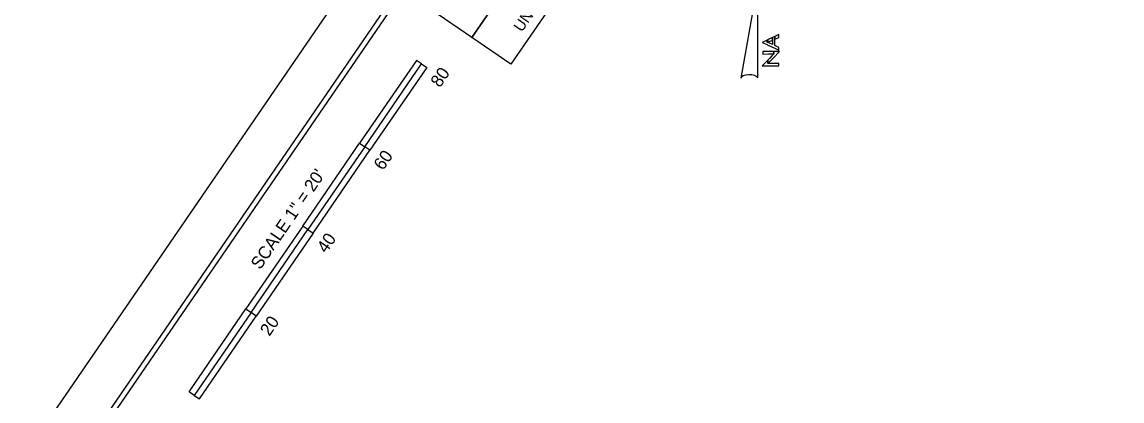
# Model space of a CAD drawing. Extents: x 1439200 to 1641919, y 393684 to 606444.
# Drawn here: x 1641394.1 to 1641613.1, y 394263 to 394338.4 of the extents above; entities that cross this region are included whole.
import ezdxf

# ---------------------------------------------------------------- set-up
doc = ezdxf.new("R2010")
doc.units = 0
for name, color, linetype in [('North Arrow NAD83 CELL', 7, 'Continuous'), ('Old_Level_20', 7, 'Continuous'), ('Old_Level_60', 7, 'Continuous'), ('Sheet Plot Border Inside CELL', 7, 'Continuous'), ('Sheet Plot Border Outside CELL', 7, 'Continuous'), ('Sheet Sticker Exception Certification CELL', 7, 'Continuous'), ('UC Plan Sheet 34 CELL', 7, 'Continuous')]:
    doc.layers.add(name, color=color, linetype=linetype)

msp = doc.modelspace()

# ---------------------------------------------------------------- linework, layer by layer
at = {"layer": 'North Arrow NAD83 CELL'}
for p, q in [((1641540.57, 394346.11), (1641537.22, 394327.22)), ((1641540.58, 394327.29), (1641540.57, 394346.11))]:
    msp.add_line(p, q, dxfattribs=at)
for points in [[(1641543.96, 394333.21), (1641544.78, 394332.83), (1641544.78, 394333.38), (1641543.96, 394333.74), (1641543.96, 394335.53), (1641543.53, 394335.33), (1641543.53, 394333.94), (1641542.8, 394334.26), (1641542.8, 394334.26), (1641542.62, 394334.33), (1641542.61, 394334.33), (1641542.44, 394334.38), (1641542.44, 394334.82), (1641541.47, 394334.37), (1641542.44, 394333.92), (1641542.62, 394333.84), (1641542.62, 394333.84), (1641542.8, 394333.75), (1641542.8, 394333.75), (1641543.53, 394333.41)], [(1641542.44, 394334.38), (1641542.61, 394334.43), (1641542.61, 394334.9), (1641542.44, 394334.82)], [(1641542.8, 394334.5), (1641543.53, 394334.82), (1641543.53, 394335.33), (1641542.8, 394334.99), (1641542.8, 394334.99), (1641542.62, 394334.9), (1641542.61, 394334.9), (1641542.61, 394334.43), (1641542.62, 394334.43), (1641542.8, 394334.5)], [(1641543.96, 394335), (1641544.78, 394335.37), (1641544.78, 394335.91), (1641543.96, 394335.53)], [(1641543.6, 394332.06), (1641543.8, 394332.06), (1641543.8, 394332.53), (1641543.6, 394332.53), (1641543.42, 394332.53), (1641542.92, 394332.53), (1641542.73, 394332.53), (1641541.6, 394332.53), (1641541.6, 394332.05), (1641542.73, 394332.06), (1641542.92, 394332.06), (1641543.42, 394332.06)], [(1641544.78, 394332.4), (1641544.9, 394332.53), (1641544.78, 394332.53), (1641543.8, 394332.53), (1641543.8, 394332.06), (1641543.6, 394331.88), (1641543.42, 394331.71), (1641542.92, 394331.19), (1641542.73, 394330.99), (1641542.57, 394330.83), (1641542.57, 394330.16), (1641542.73, 394330.29), (1641542.92, 394330.47), (1641543.42, 394330.99), (1641543.6, 394331.17), (1641543.8, 394331.39)], [(1641543.8, 394329.69), (1641544.78, 394329.69), (1641544.78, 394330.16), (1641543.8, 394330.16), (1641543.6, 394330.16), (1641543.42, 394330.16), (1641542.92, 394330.16), (1641542.73, 394330.16), (1641542.57, 394330.16), (1641542.57, 394330.83), (1641541.47, 394329.69), (1641542.57, 394329.69), (1641542.73, 394329.69), (1641542.92, 394329.69), (1641543.42, 394329.69), (1641543.6, 394329.69)]]:
    msp.add_lwpolyline(points, close=True, dxfattribs=at)
msp.add_ellipse((1641538.92, 394327.15), major_axis=(1.69, -0.01), ratio=0.461098, start_param=0.201328, end_param=3.141593, dxfattribs=at)
at = {"layer": 'Old_Level_20'}
for points in [[(1641462.35, 394313.59), (1641473.66, 394330.09), (1641472.63, 394330.79), (1641461.32, 394314.3), (1641462.35, 394313.59)], [(1641452.07, 394296.39), (1641463.38, 394312.89), (1641462.35, 394313.59), (1641451.04, 394297.1), (1641452.07, 394296.39)], [(1641439.73, 394280.61), (1641451.04, 394297.1), (1641450.01, 394297.81), (1641438.7, 394281.31), (1641439.73, 394280.61)], [(1641429.45, 394263.4), (1641440.76, 394279.9), (1641439.73, 394280.61), (1641428.42, 394264.11), (1641429.45, 394263.4)]]:
    msp.add_lwpolyline(points, dxfattribs=at)
for points in [[(1641462.35, 394313.59), (1641473.66, 394330.09), (1641474.69, 394329.38), (1641463.38, 394312.89)], [(1641450.01, 394297.81), (1641461.32, 394314.3), (1641462.35, 394313.59), (1641451.04, 394297.1)], [(1641439.73, 394280.61), (1641451.04, 394297.1), (1641452.07, 394296.39), (1641440.76, 394279.9)], [(1641427.39, 394264.82), (1641438.7, 394281.31), (1641439.73, 394280.61), (1641428.42, 394264.11)]]:
    msp.add_lwpolyline(points, close=True, dxfattribs=at)
at = {"layer": 'Old_Level_60'}
msp.add_lwpolyline([(1641470.04, 394344.7), (1641515.29, 394410.69), (1641528.94, 394401.32), (1641483.69, 394335.34)], close=True, dxfattribs=at)
at = {"layer": 'Sheet Plot Border Inside CELL'}
msp.add_lwpolyline([(1641562.49, 394481.31), (1641185.49, 393931.56), (1641533.55, 393692.87), (1641910.55, 394242.63)], close=True, dxfattribs=at)
at = {"layer": 'Sheet Plot Border Outside CELL'}
msp.add_lwpolyline([(1641556.1, 394487.87), (1641175.14, 393932.35), (1641538.02, 393683.51), (1641918.97, 394239.03)], close=True, dxfattribs=at)
at = {"layer": 'Sheet Sticker Exception Certification CELL'}
for p, q in [((1641483.69, 394335.34), (1641528.94, 394401.32)), ((1641536.7, 394396.01), (1641491.44, 394330.02)), ((1641491.44, 394330.02), (1641483.69, 394335.34))]:
    msp.add_line(p, q, dxfattribs=at)
at = {"layer": 'UC Plan Sheet 34 CELL'}
msp.add_lwpolyline([(1641560.5, 394476.61), (1641221.17, 393981.78), (1641567.55, 393744.25), (1641906.88, 394239.08)], close=True, dxfattribs=at)

# ---------------------------------------------------------------- texts
at = {"layer": 'Old_Level_20'}
for s, p in [('80', (1641477.31, 394325.23)), ('60', (1641465.99, 394308.74)), ('SCALE 1" = 20\'', (1641441.53, 394288.99)), ('40', (1641454.68, 394292.25)), ('20', (1641443.37, 394275.75))]:
    msp.add_text(s, height=2.5, rotation=55.5597, dxfattribs=at).set_placement(p)
at = {"layer": 'Sheet Sticker Exception Certification CELL'}
msp.add_text('UNLESS ALL SIGNATURES COMPLETED', height=2.2, rotation=55.5597, dxfattribs=at).set_placement((1641493.63, 394336.28))

doc.saveas('drawing.dxf')
